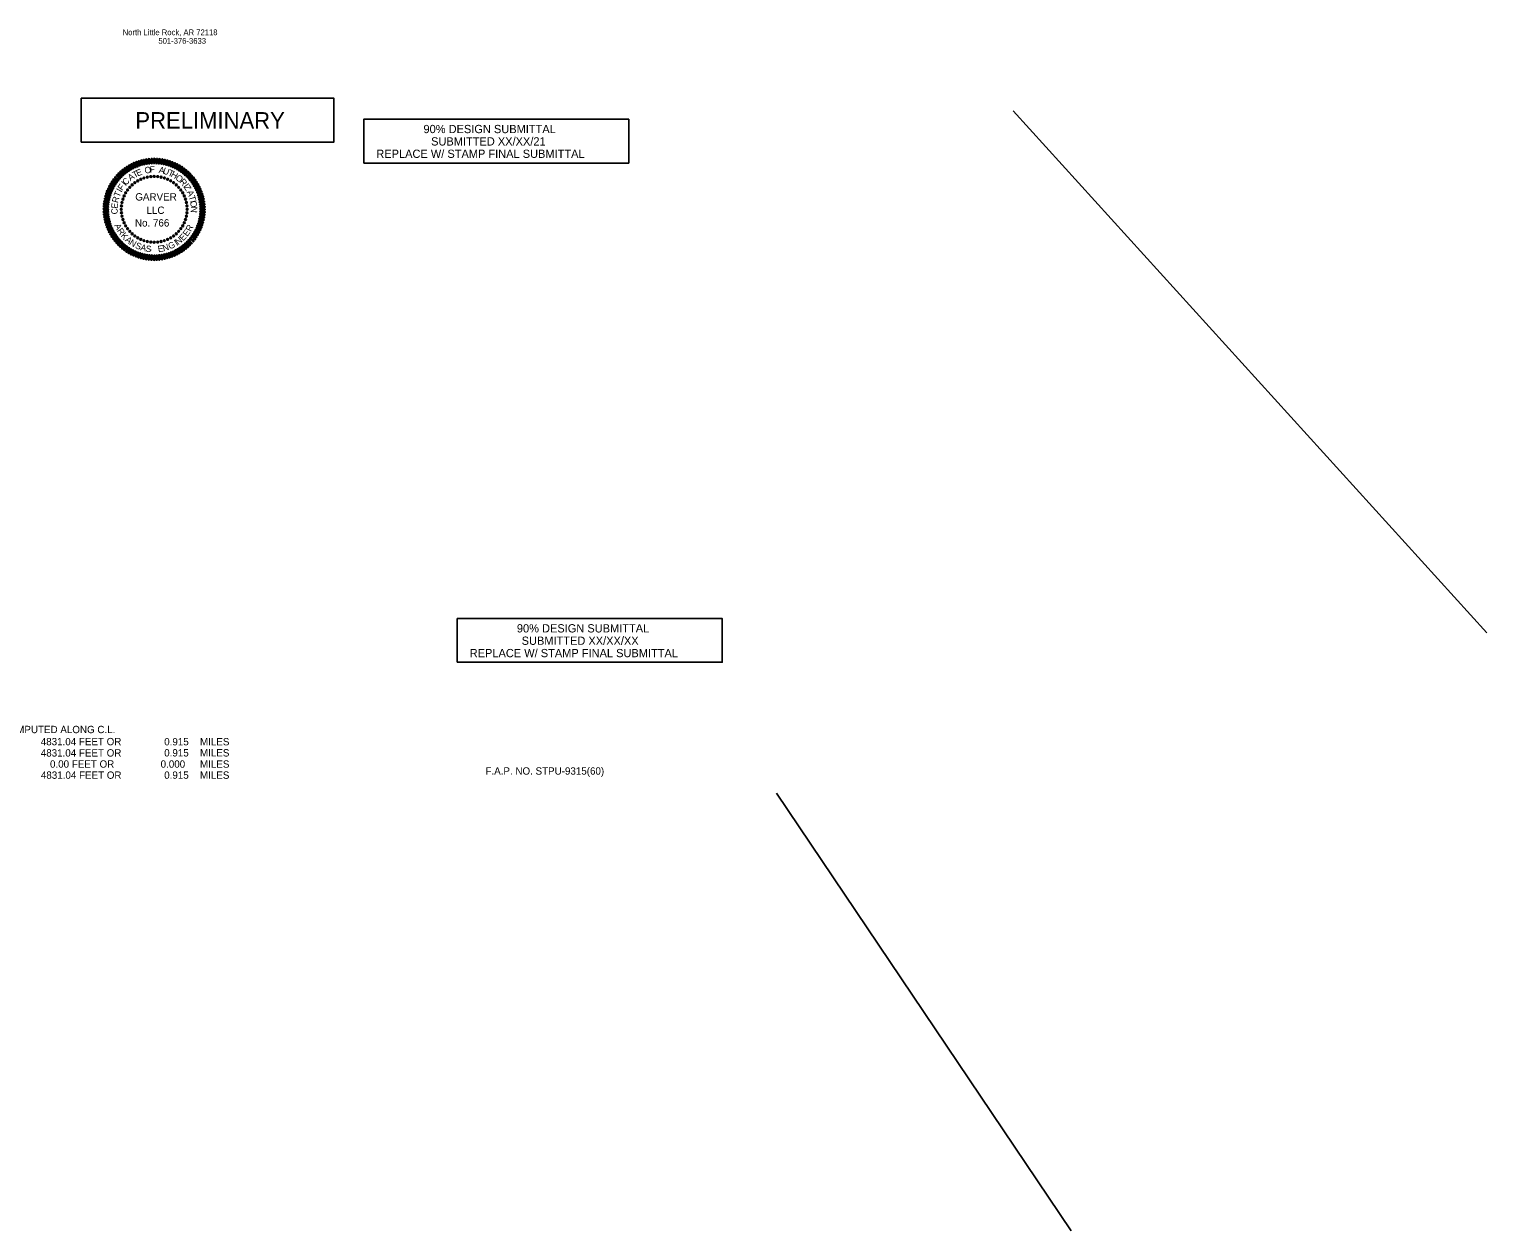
# Model space of a CAD drawing. Extents: x 1096785 to 1382432, y 216169 to 341661.
# Drawn here: x 1220535 to 1284189, y 216169 to 268627 of the extents above; entities that cross this region are included whole.
import ezdxf

# ---------------------------------------------------------------- set-up
doc = ezdxf.new("R2010")
doc.units = 0
for name, color, linetype in [('1', 7, 'Continuous'), ('14', 7, 'Continuous'), ('3', 7, 'Continuous'), ('7', 7, 'Continuous')]:
    doc.layers.add(name, color=color, linetype=linetype)

# ---------------------------------------------------------------- blocks, each defined once
blk = doc.blocks.new('SEALDO')
at = {"layer": '14'}
for radius in [0.0396, 0.0305, 0.0213, 0.0122, 0.00305]:
    blk.add_circle((1.403, -0.456), radius, dxfattribs=at)
blk = doc.blocks.new('SEALRI')
at = {"layer": '14'}
for p, q in [((-0.023, 2.258), (-0.038, 2.081)), ((-0.008, 2.281), (-0.028, 2.056)), ((0.004, 2.286), (-0.016, 2.049)), ((0.016, 2.285), (-0.004, 2.048)), ((0.028, 2.278), (0.008, 2.052)), ((0.023, 2.076), (0.038, 2.253))]:
    blk.add_line(p, q, dxfattribs=at)
for centre, start, end in [((-0.008, 2.078), 175, 355), ((0.008, 2.256), 355, 175)]:
    blk.add_arc(centre, 0.0305, start, end, dxfattribs=at)

msp = doc.modelspace()

# ---------------------------------------------------------------- linework, layer by layer
at = {"layer": '1'}
for p, q in [((1263501, 265061), (1284189, 242273)), ((1253168, 235275), (1266043, 216169))]:
    msp.add_line(p, q, dxfattribs=at)
at = {"layer": '7'}
for points in [[(1222807, 263701), (1233840, 263701), (1233840, 265613), (1222807, 265613)], [(1235150, 262784), (1246719, 262784), (1246719, 264697), (1235150, 264697)], [(1239228, 240987), (1250798, 240987), (1250798, 242899), (1239228, 242899)]]:
    msp.add_lwpolyline(points, close=True, dxfattribs=at)

# ---------------------------------------------------------------- block references
at = {"layer": '14'}
for name, xscale, yscale, rotation in [('SEALRI', 974.3980511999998, 974.3980511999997, 18.000000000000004), ('SEALRI', 974.3980511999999, 974.3980512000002, 15.000000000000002), ('SEALRI', 974.3980511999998, 974.3980511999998, 12.000000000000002), ('SEALRI', 974.3980511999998, 974.3980512, 9), ('SEALRI', 974.3980511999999, 974.3980512, 6.000000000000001), ('SEALRI', 974.3980512, 974.3980511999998, 3.000000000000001), ('SEALRI', 974.3980512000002, 974.3980511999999, -2.9999999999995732), ('SEALRI', 974.3980512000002, 974.3980512, -5.99999999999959), ('SEALRI', 974.3980511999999, 974.3980512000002, -8.999999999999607), ('SEALRI', 974.3980512, 974.3980511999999, -11.999999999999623), ('SEALRI', 974.3980512, 974.3980511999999, -14.99999999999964), ('SEALRI', 974.3980511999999, 974.3980512, -17.99999999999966), ('SEALRI', 974.3980511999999, 974.3980512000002, 48), ('SEALRI', 974.3980512, 974.3980512, 44.999999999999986), ('SEALRI', 974.3980511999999, 974.3980512, 41.999999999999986), ('SEALRI', 974.3980512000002, 974.3980511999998, 38.999999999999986), ('SEALRI', 974.3980511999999, 974.3980512, 35.99999999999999), ('SEALRI', 974.3980512, 974.3980511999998, 33), ('SEALRI', 974.3980511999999, 974.3980511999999, 30.000000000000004), ('SEALRI', 974.3980512, 974.3980512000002, 26.999999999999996), ('SEALRI', 974.3980511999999, 974.3980512, 23.999999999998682), ('SEALRI', 974.3980512, 974.3980511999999, 20.999999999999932), ('SEALRI', 974.3980511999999, 974.3980512, -20.999999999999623), ('SEALRI', 974.3980512, 974.3980512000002, -23.999999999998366), ('SEALRI', 974.3980512, 974.3980511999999, -26.99999999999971), ('SEALRI', 974.3980511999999, 974.3980511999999, -29.99999999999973), ('SEALRI', 974.3980512, 974.3980512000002, -32.999999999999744), ('SEALRI', 974.3980511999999, 974.3980511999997, -35.99999999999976), ('SEALRI', 974.3980511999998, 974.3980512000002, -38.99999999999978), ('SEALRI', 974.3980511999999, 974.3980512, -41.99999999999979), ('SEALRI', 974.3980512, 974.3980512, -44.99999999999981), ('SEALRI', 974.3980512, 974.3980512, -47.99999999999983), ('SEALRI', 974.3980512, 974.3980512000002, 65.99999999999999), ('SEALRI', 974.3980511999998, 974.3980512, 63), ('SEALRI', 974.3980511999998, 974.3980512, 59.999999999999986), ('SEALRI', 974.3980512, 974.3980512, 56.999999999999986), ('SEALRI', 974.3980511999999, 974.3980512, 54.00000000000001), ('SEALRI', 974.3980511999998, 974.3980512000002, 50.999999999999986), ('SEALDO', 974.3980511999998, 974.3980512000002, 162.00000000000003), ('SEALDO', 974.3980512, 974.3980512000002, 156.00000000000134), ('SEALDO', 974.3980512, 974.3980512, 150), ('SEALDO', 974.3980511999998, 974.3980512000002, 144), ('SEALDO', 974.3980511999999, 974.3980512, 138), ('SEALDO', 974.3980511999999, 974.3980512, 131.99999999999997), ('SEALDO', 974.3980512, 974.3980512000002, 125.99999999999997), ('SEALDO', 974.3980511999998, 974.3980511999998, 119.99999999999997), ('SEALDO', 974.3980511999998, 974.3980512, 113.99999999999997), ('SEALDO', 974.3980511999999, 974.3980512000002, 107.99999999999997), ('SEALDO', 974.3980511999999, 974.3980512, 101.99999999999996), ('SEALDO', 974.3980511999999, 974.3980511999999, 95.99999999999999), ('SEALDO', 974.3980512, 974.3980512, 90), ('SEALDO', 974.3980511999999, 974.3980512, 83.99999999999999), ('SEALDO', 974.3980511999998, 974.3980512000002, 77.99999999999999), ('SEALDO', 974.3980511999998, 974.3980511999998, 72), ('SEALDO', 974.3980512, 974.3980512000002, 66.00000000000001), ('SEALDO', 974.3980512, 974.3980512, 60.00000000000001), ('SEALDO', 974.3980511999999, 974.3980512, 54.00000000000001), ('SEALRI', 974.3980511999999, 974.3980512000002, -50.99999999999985), ('SEALRI', 974.3980512, 974.3980511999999, -53.99999999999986), ('SEALRI', 974.3980512, 974.3980512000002, -56.999999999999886), ('SEALRI', 974.3980511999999, 974.3980512, -59.99999999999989), ('SEALRI', 974.3980511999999, 974.3980512, -62.99999999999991), ('SEALRI', 974.3980512, 974.3980512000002, -65.99999999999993), ('SEALRI', 974.3980511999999, 974.3980511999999, 84.00000000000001), ('SEALRI', 974.3980512, 974.3980511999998, 81), ('SEALRI', 974.3980511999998, 974.3980511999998, 78.00000000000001), ('SEALRI', 974.3980511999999, 974.3980511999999, 75.00000000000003), ('SEALRI', 974.3980511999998, 974.3980511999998, 72), ('SEALRI', 974.3980512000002, 974.3980512, 68.99999999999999), ('SEALDO', 974.3980512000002, 974.3980511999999, -173.99999999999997), ('SEALDO', 974.3980512, 974.3980512, -179.99999999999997), ('SEALDO', 974.3980511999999, 974.3980511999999, 174.00000000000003), ('SEALDO', 974.3980511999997, 974.3980511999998, 168.00000000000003), ('SEALDO', 974.3980512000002, 974.3980512, 48.00000000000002), ('SEALDO', 974.3980511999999, 974.3980512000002, 42.00000000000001), ('SEALDO', 974.3980511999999, 974.3980512, 35.99999999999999), ('SEALDO', 974.3980512, 974.3980512, 29.999999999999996), ('SEALRI', 974.3980511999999, 974.3980512, -68.99999999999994), ('SEALRI', 974.3980511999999, 974.3980512, -71.99999999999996), ('SEALRI', 974.3980512, 974.3980512, -74.99999999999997), ('SEALRI', 974.3980511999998, 974.3980512, -78), ('SEALRI', 974.3980511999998, 974.3980511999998, -81.00000000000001), ('SEALRI', 974.3980511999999, 974.3980511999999, -84.00000000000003), ('SEALRI', 974.3980512, 974.3980512, 90.00000000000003), ('SEALRI', 974.3980512, 974.3980512, 87.00000000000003), ('SEALRI', 974.3980512, 974.3980511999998, 93), ('SEALRI', 974.3980511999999, 974.3980512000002, 96.00000000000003), ('SEALRI', 974.3980511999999, 974.3980511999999, 99.00000000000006), ('SEALRI', 974.3980511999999, 974.3980511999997, 102.00000000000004), ('SEALDO', 974.3980511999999, 974.3980511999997, -161.9999999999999), ('SEALDO', 974.3980512, 974.3980512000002, -156.00000000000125), ('SEALDO', 974.3980511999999, 974.3980512, -167.99999999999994), ('SEALDO', 974.3980512, 974.3980512, -149.99999999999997), ('SEALDO', 974.3980512, 974.3980512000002, -143.99999999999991), ('SEALDO', 974.3980511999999, 974.3980512, 6.000000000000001), ('SEALDO', 974.3980511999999, 974.3980512, 23.99999999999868), ('SEALDO', 974.3980511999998, 974.3980511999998, 12.000000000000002), ('SEALDO', 974.3980511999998, 974.3980511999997, 18.000000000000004), ('SEALRI', 974.3980511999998, 974.3980512, -102.00000000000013), ('SEALRI', 974.3980512, 974.3980511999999, -99.00000000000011), ('SEALRI', 974.3980512, 974.3980512, -96.0000000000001), ('SEALRI', 974.3980512, 974.3980512, -87.00000000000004), ('SEALRI', 974.3980512, 974.3980511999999, -93.00000000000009), ('SEALRI', 974.3980512, 974.3980512, -90.00000000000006), ('SEALRI', 974.3980512, 974.3980511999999, 105.00000000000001), ('SEALRI', 974.3980511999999, 974.3980512, 108.00000000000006), ('SEALRI', 974.3980511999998, 974.3980512, 111.00000000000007), ('SEALRI', 974.3980512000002, 974.3980512, 114.00000000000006), ('SEALRI', 974.3980511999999, 974.3980512, 117.00000000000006), ('SEALRI', 974.3980511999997, 974.3980511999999, 120.00000000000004), ('SEALDO', 974.3980512, 974.3980512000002, -137.99999999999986), ('SEALDO', 974.3980512, 974.3980511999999, -131.99999999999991), ('SEALDO', 974.3980512, 974.3980511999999, -125.9999999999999), ('SEALDO', 974.3980511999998, 974.3980511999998, -119.99999999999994), ('SEALDO', 974.3980512, 974.3980512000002, -113.99999999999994), ('SEALDO', 974.3980511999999, 974.3980511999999, -30.00000000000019), ('SEALDO', 974.3980512, 974.3980511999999, -23.999999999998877), ('SEALDO', 974.3980511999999, 974.3980512, -18.000000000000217), ('SEALDO', 974.3980511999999, 974.3980511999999, -12.000000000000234), ('SEALDO', 974.3980511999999, 974.3980512, -6.000000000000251), ('SEALRI', 974.3980511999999, 974.3980512, -120.00000000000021), ('SEALRI', 974.3980511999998, 974.3980511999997, -117.00000000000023), ('SEALRI', 974.3980512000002, 974.3980512, -114.0000000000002), ('SEALRI', 974.3980511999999, 974.3980511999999, -111.00000000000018), ('SEALRI', 974.3980512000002, 974.3980511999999, -108.00000000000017), ('SEALRI', 974.3980512, 974.3980511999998, -105.00000000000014), ('SEALRI', 974.3980511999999, 974.3980511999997, 123.00000000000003), ('SEALRI', 974.3980512, 974.3980512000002, 126.00000000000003), ('SEALRI', 974.3980511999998, 974.3980512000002, 129.00000000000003), ('SEALRI', 974.3980511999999, 974.3980512, 132), ('SEALRI', 974.3980511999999, 974.3980511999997, 135), ('SEALRI', 974.3980511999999, 974.3980512, 138), ('SEALRI', 974.3980512, 974.3980511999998, 140.99999999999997), ('SEALRI', 974.3980511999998, 974.3980512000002, 144), ('SEALRI', 974.3980511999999, 974.3980512, 146.99999999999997), ('SEALDO', 974.3980511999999, 974.3980512, -107.99999999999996), ('SEALDO', 974.3980511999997, 974.3980511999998, -101.99999999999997), ('SEALDO', 974.3980511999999, 974.3980512, -96), ('SEALDO', 974.3980512, 974.3980512, -90.00000000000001), ('SEALDO', 974.3980511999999, 974.3980511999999, -84.00000000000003), ('SEALDO', 974.3980511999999, 974.3980512, -78.00000000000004), ('SEALDO', 974.3980511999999, 974.3980511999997, -72.00000000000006), ('SEALDO', 974.3980512, 974.3980511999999, -66.00000000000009), ('SEALDO', 974.3980511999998, 974.3980512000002, -60.0000000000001), ('SEALDO', 974.3980512, 974.3980511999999, -54.000000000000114), ('SEALDO', 974.3980512, 974.3980511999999, -48.000000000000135), ('SEALDO', 974.3980511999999, 974.3980511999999, -42.00000000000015), ('SEALDO', 974.3980511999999, 974.3980512, -36.00000000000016), ('SEALRI', 974.3980512, 974.3980512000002, -147.00000000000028), ('SEALRI', 974.3980512, 974.3980511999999, -144.00000000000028), ('SEALRI', 974.3980511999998, 974.3980512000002, -141.00000000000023), ('SEALRI', 974.3980512, 974.3980511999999, -138.00000000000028), ('SEALRI', 974.3980511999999, 974.3980512, -135.00000000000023), ('SEALRI', 974.3980512, 974.3980511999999, -132.00000000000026), ('SEALRI', 974.3980511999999, 974.3980511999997, -129.00000000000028), ('SEALRI', 974.3980512, 974.3980512, -126.00000000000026), ('SEALRI', 974.3980512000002, 974.3980512, -123.00000000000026), ('SEALRI', 974.3980511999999, 974.3980512, 149.99999999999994), ('SEALRI', 974.3980512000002, 974.3980512, 152.99999999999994), ('SEALRI', 974.3980512, 974.3980511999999, 156.00000000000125), ('SEALRI', 974.3980511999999, 974.3980512, 159), ('SEALRI', 974.3980511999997, 974.3980511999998, 161.99999999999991), ('SEALRI', 974.3980511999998, 974.3980512, 164.99999999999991), ('SEALRI', 974.3980511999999, 974.3980511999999, 167.99999999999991), ('SEALRI', 974.3980512, 974.3980511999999, 170.9999999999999), ('SEALRI', 974.3980512, 974.3980512, 173.9999999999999), ('SEALRI', 974.3980512, 974.3980512, 176.9999999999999), ('SEALRI', 974.3980512, 974.3980512, 179.99999999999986), ('SEALRI', 974.3980512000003, 974.3980512, -177.00000000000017), ('SEALRI', 974.3980512, 974.3980512, -174.00000000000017), ('SEALRI', 974.3980511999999, 974.3980512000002, -171.00000000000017), ('SEALRI', 974.3980511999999, 974.3980512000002, -168.0000000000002), ('SEALRI', 974.3980511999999, 974.3980512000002, -165.0000000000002), ('SEALRI', 974.3980511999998, 974.3980512, -162.00000000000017), ('SEALRI', 974.3980511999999, 974.3980512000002, -159.00000000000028), ('SEALRI', 974.3980512, 974.3980512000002, -156.00000000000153), ('SEALRI', 974.3980512, 974.3980511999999, -153.0000000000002), ('SEALRI', 974.3980512, 974.3980511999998, -150.00000000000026)]:
    msp.add_blockref(name, (1225996, 260762), dxfattribs=dict(at, xscale=xscale, yscale=yscale, rotation=rotation))
at = {"layer": '14', "xscale": 974.3980512, "yscale": 974.3980512}
for name in ['SEALRI', 'SEALDO']:
    msp.add_blockref(name, (1225996, 260762), dxfattribs=at)

# ---------------------------------------------------------------- texts
at = {"layer": '1'}
for s, height, p in [('PRELIMINARY', 720, (1225173, 264285)), ('90% DESIGN SUBMITTAL', 360, (1237755, 264088)), ('SUBMITTED XX/XX/21', 360, (1238087, 263548)), ('REPLACE W/ STAMP FINAL SUBMITTAL', 360, (1235695, 263008)), ('90% DESIGN SUBMITTAL', 360, (1241834, 242291)), ('SUBMITTED XX/XX/XX', 360, (1242041, 241751)), ('REPLACE W/ STAMP FINAL SUBMITTAL', 360, (1239773, 241211))]:
    msp.add_text(s, height=height, dxfattribs=at).set_placement(p)
at = {"layer": '14'}
for s, rotation, p in [('A', 34.94377, (1224959, 261988)), ('T', 28.2771, (1225136, 262116)), ('E', 21.61044, (1225270, 262195)), ('O', 8.2771, (1225593, 262320)), ('F', 1.61044, (1225804, 262356)), ('A', 348.2771, (1226176, 262359)), ('U', 341.27715, (1226350, 262331)), ('T', 334.94377, (1226569, 262260)), ('H', 328.2771, (1226694, 262211)), ('O', 319.7874, (1226896, 262097)), ('I', 61.61044, (1224569, 261484)), ('F', 54.94377, (1224602, 261559)), ('I', 49.74076, (1224747, 261763)), ('C', 44.38813, (1224761, 261792)), ('R', 311.99331, (1227078, 261951)), ('I', 307.00814, (1227248, 261760)), ('Z', 301.61044, (1227281, 261726)), ('E', 83.89849, (1224390, 260785)), ('R', 74.94377, (1224410, 261023)), ('T', 67.43139, (1224475, 261268)), ('A', 292.97516, (1227412, 261524)), ('T', 286.3085, (1227499, 261323)), ('I', 281.61044, (1227555, 261127)), ('O', 276.48226, (1227566, 261117)), ('C', 91.88416, (1224403, 260547)), ('N', 268.2771, (1227601, 260882)), ('A', 296.57465, (1224248, 260057)), ('R', 304.61826, (1224358, 259827)), ('K', 313.3805, (1224514, 259594)), ('E', 46.68075, (1227261, 259364)), ('E', 54.73091, (1227445, 259554)), ('R', 63.09594, (1227600, 259768)), ('A', 321.25836, (1224703, 259391)), ('N', 329.10994, (1224886, 259237)), ('S', 337.62936, (1225143, 259080)), ('A', 345.40726, (1225377, 258982)), ('S', 352.80457, (1225613, 258915)), ('E', 10.06947, (1226178, 258886)), ('N', 17.86862, (1226411, 258920)), ('G', 26.41319, (1226686, 259005)), ('I', 32.97899, (1226981, 259161)), ('N', 38.98211, (1227046, 259194)), ('-', 0.83848, (1225781, 258879))]:
    msp.add_text(s, height=278, rotation=rotation, dxfattribs=at).set_placement(p)
for s, p in [('GARVER', (1225169, 261146)), ('LLC', (1225659, 260563)), ('No. 766', (1225155, 260011))]:
    msp.add_text(s, height=320.8, dxfattribs=at).set_placement(p)
at = {"layer": '3'}
for s, height, p in [('North Little Rock, AR 72118', 250, (1224617, 268364)), ('501-376-3633', 250, (1226178, 267989)), ('4831.04 FEET OR', 320, (1221042, 237366)), ('0.915', 320, (1226433, 237362)), ('MILES', 320, (1227995, 237362)), ('4831.04 FEET OR', 320, (1221043, 236873)), ('0.915', 320, (1226433, 236876)), ('MILES', 320, (1227995, 236876)), ('4831.04 FEET OR', 320, (1221048, 235903)), (' 0.00 FEET OR', 320, (1221327, 236388)), ('0.000', 320, (1226277, 236386)), ('0.915', 320, (1226433, 235903)), ('MILES', 320, (1227995, 236386)), ('MILES', 320, (1227995, 235903))]:
    msp.add_text(s, height=height, rotation=360, dxfattribs=at).set_placement(p)
for s, p in [('LENGTH COMPUTED ALONG C.L.', (1217475, 237895)), ('F.A.P. NO. STPU-9315(60)', (1240461, 236084))]:
    msp.add_text(s, height=320, dxfattribs=at).set_placement(p)

doc.saveas('drawing.dxf')
